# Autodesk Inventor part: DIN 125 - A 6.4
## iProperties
Comments: To add or edit properties for Autodesk Inventor files, use iProperties.
Created: 2004-02
Part Number: DIN 125 - A 6.4
Vendor: Autodesk Inc.
Document SubType Name: Modeling
Designer: Administrator
Material: A4
Description: Scheibe
Standard: DIN 125
Manufacturer: Standard
Standards Organization: Custom
Alert: To add or edit properties for Autodesk Inventor files, use iProperties.
Control State: 0
Master: False
Checked Out: False
Shininess: 64.0
Length Units: 11269
Angle Units: 11279
Time Units: 11290
Mass Units: 11283
Length Display Precision: 3
Angle Display Precision: 2
Compacted: True
Classification: un/spsc 31161807
ArtNr: L29920
Farbe: Metal-Steel
Zuschnitt: 2mm
GesGewicht: 0,0kg
Zeichnungsnummer: DIN 125 - A 6.4
Density: 0.0
Volumn: 0.0
Area: 0.0
PropertySet Name: Model Information
Author: Administrator
Revision Number: 5
Title: Scheibe für M6
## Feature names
1. Körper [Extrusion]
